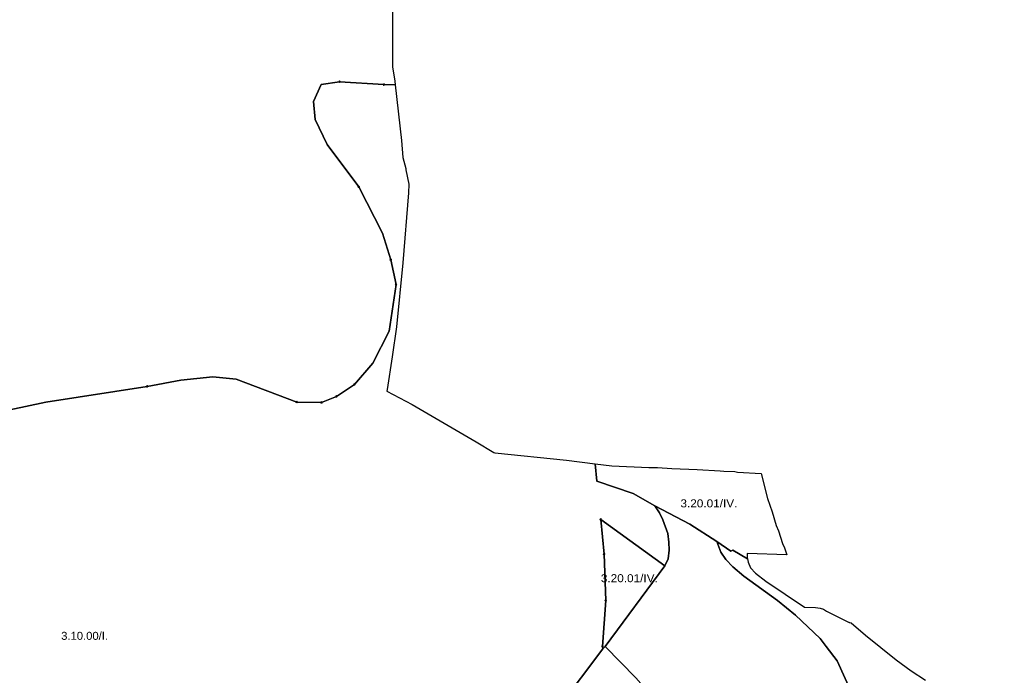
# Model space of a CAD drawing. Extents: x -650455 to -642254, y -1075222 to -1066610.
# Drawn here: x -645652 to -644431, y -1072036 to -1071216 of the extents above; entities that cross this region are included whole.
import ezdxf
from ezdxf.enums import TextEntityAlignment as Align

# ---------------------------------------------------------------- set-up
doc = ezdxf.new("R2010")
doc.units = 0
doc.header["$LTSCALE"] = 4
doc.header["$PDMODE"] = 32
doc.header["$PDSIZE"] = 2
for name, color, linetype, lineweight in [('1', 7, 'Continuous', 25), ('11', 7, 'Continuous', 13), ('12', 7, 'Continuous', 13), ('13', 7, 'Continuous', 13), ('14', 7, 'Continuous', 13)]:
    doc.layers.add(name, color=color, linetype=linetype, lineweight=lineweight)
doc.layers.add('2', color=7, linetype='Continuous')

msp = doc.modelspace()

# ---------------------------------------------------------------- linework, layer by layer
at = {"layer": '1'}
for points in [[(-645186.478, -1071047.655), (-645186.168, -1071275.322), (-645183.374, -1071293.336), (-645182.879, -1071297.884), (-645197, -1071297.501), (-645252.5, -1071294.001), (-645275.5, -1071297.501), (-645285, -1071318.501), (-645283, -1071341), (-645268, -1071372.5), (-645228.5, -1071425.5), (-645199, -1071483.501), (-645188.5, -1071516.501), (-645182, -1071547.5), (-645190.5, -1071606.001), (-645211, -1071646.001), (-645234, -1071672.5), (-645256.5, -1071687.5), (-645275, -1071695.001), (-645306, -1071694.501), (-645381.5, -1071666.001), (-645411, -1071663), (-645451, -1071667.001), (-645493, -1071675.001), (-645619.5, -1071694.501), (-645762.5, -1071725)], [(-645381.5, -1071666.001), (-645306, -1071694.501), (-645275, -1071695.001), (-645256.5, -1071687.5), (-645234, -1071672.5), (-645211, -1071646.001), (-645190.5, -1071606.001), (-645182, -1071547.5), (-645188.5, -1071516.501), (-645199, -1071483.501), (-645228.5, -1071425.5), (-645268, -1071372.5), (-645283, -1071341), (-645285, -1071318.501), (-645275.5, -1071297.501), (-645252.5, -1071294.001), (-645197, -1071297.501), (-645182.879, -1071297.884)], [(-645182.879, -1071297.884), (-645175.302, -1071367.569), (-645173.594, -1071388.835), (-645169.822, -1071402.466), (-645169.513, -1071403.966), (-645165.827, -1071421.836), (-645166.41, -1071432.918), (-645173.6, -1071520.205), (-645181.567, -1071600.493), (-645186.619, -1071637.819), (-645193.199, -1071679.003), (-645193.481, -1071680.767), (-645161.645, -1071697.751), (-645081.726, -1071744.088), (-645059.979, -1071757.758), (-645058.478, -1071757.915), (-644969.167, -1071767.179), (-644933.238, -1071771.647), (-644931.066, -1071793.462), (-644885.697, -1071809.017), (-644858.507, -1071824.054), (-644852.999, -1071832.972), (-644848.802, -1071841.89), (-644842.508, -1071858.851), (-644841.109, -1071869.867), (-644840.584, -1071879.659), (-644841.808, -1071890.5), (-644846.005, -1071899.418), (-644926.312, -1071841.204), (-644922, -1071884.501), (-644920, -1071942.5), (-644924, -1072000), (-644923.589, -1072003.101), (-644978.202, -1072075.468)], [(-645762.5, -1071725), (-645619.5, -1071694.501), (-645493, -1071675.001), (-645451, -1071667.001), (-645411, -1071663), (-645381.5, -1071666.001)], [(-644841.196, -1072085.989), (-644882.287, -1072039.303), (-644920.668, -1072000), (-644846.005, -1071899.418), (-644841.808, -1071890.5), (-644840.584, -1071879.659), (-644841.109, -1071869.867), (-644842.508, -1071858.851), (-644848.802, -1071841.89), (-644852.999, -1071832.972), (-644858.507, -1071824.054), (-644814.968, -1071847.135), (-644781.395, -1071868.992)], [(-644431.857, -1072311.904), (-644430.633, -1072298.615), (-644431.682, -1072288.473), (-644436.403, -1072278.331), (-644453.627, -1072249.305), (-644492.882, -1072176.04), (-644584.42, -1072108.721), (-644596.572, -1072092.634), (-644604.965, -1072074.973), (-644630.931, -1072017.97), (-644644.606, -1072000), (-644652.089, -1071990.168), (-644682.776, -1071960.792), (-644705.508, -1071942.607), (-644747.386, -1071912.357), (-644761.374, -1071900.641), (-644769.942, -1071891.374), (-644776.237, -1071882.107), (-644781.395, -1071868.992), (-644763.822, -1071881.057), (-644761.199, -1071879.659), (-644742.849, -1071890.721)], [(-644781.395, -1071868.992), (-644776.237, -1071882.107), (-644769.942, -1071891.374), (-644761.374, -1071900.641), (-644747.386, -1071912.357), (-644705.508, -1071942.607), (-644682.776, -1071960.792), (-644652.089, -1071990.168), (-644644.606, -1072000), (-644630.931, -1072017.97), (-644604.965, -1072074.973)], [(-644742.849, -1071890.721), (-644742.106, -1071894.882), (-644739.294, -1071901.811), (-644733.02, -1071908.305), (-644720.041, -1071918.372), (-644671.801, -1071950.845), (-644657.871, -1071951.331), (-644651.944, -1071952.178), (-644647.993, -1071953.447), (-644644.042, -1071955.847), (-644616.666, -1071969.818), (-644615.96, -1071969.818), (-644615.819, -1071970.24), (-644613.279, -1071970.664), (-644595.358, -1071985.904), (-644557.257, -1072016.666), (-644538.207, -1072030.496), (-644520.385, -1072042.196)], [(-644978.202, -1072075.468), (-644923.589, -1072003.101), (-644920.668, -1072000), (-644882.287, -1072039.303)]]:
    msp.add_lwpolyline(points, dxfattribs=at)
for points in [[(-644696.536, -1071876.964), (-644693.695, -1071885.72), (-644743.234, -1071883.988), (-644743.22, -1071885.489), (-644743.188, -1071888.822), (-644742.849, -1071890.721), (-644761.199, -1071879.659), (-644763.822, -1071881.057), (-644781.395, -1071868.992), (-644814.968, -1071847.135), (-644858.507, -1071824.054), (-644885.697, -1071809.017), (-644931.066, -1071793.462), (-644933.238, -1071771.647), (-644912.439, -1071774.234), (-644866.154, -1071776.35), (-644855.43, -1071776.493), (-644837.367, -1071777.762), (-644805.758, -1071778.75), (-644776.971, -1071780.443), (-644772.455, -1071781.007), (-644758.908, -1071781.432), (-644755.38, -1071782.136), (-644725.862, -1071783.887), (-644718.089, -1071814.991), (-644712.2, -1071831.95), (-644707.119, -1071848.884), (-644704.297, -1071855.657), (-644699.076, -1071871.462)], [(-644846.005, -1071899.418), (-644920.668, -1072000), (-644923.589, -1072003.101), (-644924, -1072000), (-644920, -1071942.5), (-644922, -1071884.501), (-644926.312, -1071841.204)]]:
    msp.add_lwpolyline(points, close=True, dxfattribs=at)
at = {"layer": '11'}
msp.add_line((-645256.5, -1071687.5), (-645275, -1071695.001), dxfattribs=at)
for points in [[(-645197, -1071297.501), (-645182.879, -1071297.884), (-645183.374, -1071293.336), (-645186.168, -1071275.322), (-645186.478, -1071047.655), (-645173.128, -1071048.276), (-645170.955, -1070998.27), (-645169.092, -1070971.559), (-645147.987, -1070978.586), (-645084.341, -1070986.35), (-645003.309, -1070990.698), (-644922.588, -1070989.767)], [(-645252.5, -1071294.001), (-645275.5, -1071297.501), (-645285, -1071318.501), (-645283, -1071341), (-645268, -1071372.5), (-645228.5, -1071425.5)], [(-645188.5, -1071516.501), (-645199, -1071483.501), (-645228.5, -1071425.5), (-645268, -1071372.5), (-645283, -1071341), (-645285, -1071318.501), (-645275.5, -1071297.501), (-645252.5, -1071294.001), (-645197, -1071297.501)], [(-644922, -1071884.501), (-644926.312, -1071841.204), (-644846.005, -1071899.418), (-644841.808, -1071890.5), (-644840.584, -1071879.659), (-644841.109, -1071869.867), (-644842.508, -1071858.851), (-644848.802, -1071841.89), (-644852.999, -1071832.972), (-644858.507, -1071824.054), (-644885.697, -1071809.017), (-644931.066, -1071793.462), (-644933.238, -1071771.647), (-644969.167, -1071767.179), (-645058.478, -1071757.915), (-645059.979, -1071757.758), (-645081.726, -1071744.088), (-645161.645, -1071697.751), (-645193.481, -1071680.767), (-645193.199, -1071679.003), (-645186.619, -1071637.819), (-645181.567, -1071600.493), (-645173.6, -1071520.205), (-645166.41, -1071432.918), (-645165.827, -1071421.836), (-645169.513, -1071403.966), (-645169.822, -1071402.466), (-645173.594, -1071388.835), (-645175.302, -1071367.569), (-645182.879, -1071297.884), (-645197, -1071297.501), (-645252.5, -1071294.001)], [(-645228.5, -1071425.5), (-645199, -1071483.501), (-645188.5, -1071516.501), (-645182, -1071547.5)], [(-645234, -1071672.5), (-645211, -1071646.001), (-645190.5, -1071606.001), (-645182, -1071547.5), (-645188.5, -1071516.501)], [(-645182, -1071547.5), (-645190.5, -1071606.001), (-645211, -1071646.001), (-645234, -1071672.5), (-645256.5, -1071687.5)], [(-645837, -1071732.5), (-645792, -1071731.001), (-645762.5, -1071725), (-645619.5, -1071694.501), (-645493, -1071675.001), (-645451, -1071667.001), (-645411, -1071663), (-645381.5, -1071666.001), (-645306, -1071694.501)], [(-645275, -1071695.001), (-645306, -1071694.501), (-645381.5, -1071666.001), (-645411, -1071663), (-645451, -1071667.001), (-645493, -1071675.001)], [(-645493, -1071675.001), (-645619.5, -1071694.501), (-645762.5, -1071725), (-645792, -1071731.001), (-645837, -1071732.5), (-645877.5, -1071728), (-645913.5, -1071713), (-645940, -1071694.501), (-645954.5, -1071680.5)], [(-645306, -1071694.501), (-645275, -1071695.001), (-645256.5, -1071687.5), (-645234, -1071672.5)], [(-644924, -1072000), (-644920, -1071942.5), (-644922, -1071884.501)], [(-645000, -1072668.218), (-644963.5, -1072659), (-644952, -1072647.5), (-644985.633, -1072565.416), (-644974.792, -1072562.094), (-644960.629, -1072570.487), (-644946.5, -1072572.001), (-644939, -1072559.5), (-644932, -1072501.001), (-644934, -1072451.501), (-644939.5, -1072388.5), (-644942.5, -1072307.5), (-644938, -1072258.001), (-644932.308, -1072244.028), (-645000, -1072103.795), (-644978.202, -1072075.468), (-644923.589, -1072003.101), (-644924, -1072000)]]:
    msp.add_lwpolyline(points, dxfattribs=at)
for p in [(-645252.5, -1071294.001), (-645197, -1071297.501), (-645228.5, -1071425.5), (-645188.5, -1071516.501), (-645182, -1071547.5), (-645493, -1071675.001), (-645234, -1071672.5), (-645256.5, -1071687.5), (-645306, -1071694.501), (-645275, -1071695.001), (-644922, -1071884.501), (-644924, -1072000)]:
    msp.add_point(p, dxfattribs=at)
at = {"layer": '12'}
msp.add_lwpolyline([(-644604.965, -1072074.973), (-644630.931, -1072017.97), (-644644.606, -1072000), (-644652.089, -1071990.168), (-644682.776, -1071960.792), (-644705.508, -1071942.607), (-644747.386, -1071912.357), (-644761.374, -1071900.641), (-644769.942, -1071891.374), (-644776.237, -1071882.107), (-644781.395, -1071868.992), (-644814.968, -1071847.135), (-644858.507, -1071824.054), (-644852.999, -1071832.972), (-644848.802, -1071841.89), (-644842.508, -1071858.851), (-644841.109, -1071869.867), (-644840.584, -1071879.659), (-644841.808, -1071890.5), (-644846.005, -1071899.418), (-644920.668, -1072000), (-644882.287, -1072039.303)], dxfattribs=at)
at = {"layer": '13'}
for points in [[(-644520.385, -1072042.196), (-644538.207, -1072030.496), (-644557.257, -1072016.666), (-644595.358, -1071985.904), (-644613.279, -1071970.664), (-644615.819, -1071970.24), (-644615.96, -1071969.818), (-644616.666, -1071969.818), (-644644.042, -1071955.847), (-644647.993, -1071953.447), (-644651.944, -1071952.178), (-644657.871, -1071951.331), (-644671.801, -1071950.845), (-644720.041, -1071918.372), (-644733.02, -1071908.305), (-644739.294, -1071901.811), (-644742.106, -1071894.882), (-644742.849, -1071890.721), (-644761.199, -1071879.659), (-644763.822, -1071881.057), (-644781.395, -1071868.992), (-644776.237, -1071882.107), (-644769.942, -1071891.374), (-644761.374, -1071900.641), (-644747.386, -1071912.357), (-644705.508, -1071942.607), (-644682.776, -1071960.792), (-644652.089, -1071990.168), (-644644.606, -1072000), (-644630.931, -1072017.97), (-644604.965, -1072074.973)], [(-644662.318, -1072275.534), (-644684.088, -1072253.327), (-644708.393, -1072229.022), (-644740.129, -1072182.51), (-644750.62, -1072169.92), (-644789.351, -1072136.698), (-644812.607, -1072115.89), (-644841.196, -1072085.989), (-644882.287, -1072039.303), (-644920.668, -1072000), (-644923.589, -1072003.101), (-644978.202, -1072075.468), (-644931.428, -1072113.412), (-644907.123, -1072134.745), (-644885.79, -1072150.832), (-644855.103, -1072180.732), (-644741.009, -1072287.394), (-644719.414, -1072308.552)]]:
    msp.add_lwpolyline(points, dxfattribs=at)
at = {"layer": '14'}
msp.add_line((-644920, -1071942.5), (-644924, -1072000), dxfattribs=at)
msp.add_lwpolyline([(-644781.395, -1071868.992), (-644763.822, -1071881.057), (-644761.199, -1071879.659), (-644742.849, -1071890.721), (-644743.188, -1071888.822), (-644743.22, -1071885.489), (-644743.234, -1071883.988), (-644693.695, -1071885.72), (-644696.536, -1071876.964), (-644699.076, -1071871.462), (-644704.297, -1071855.657), (-644707.119, -1071848.884), (-644712.2, -1071831.95), (-644718.089, -1071814.991), (-644725.862, -1071783.887), (-644755.38, -1071782.136), (-644758.908, -1071781.432), (-644772.455, -1071781.007), (-644776.971, -1071780.443), (-644805.758, -1071778.75), (-644837.367, -1071777.762), (-644855.43, -1071776.493), (-644866.154, -1071776.35), (-644912.439, -1071774.234), (-644933.238, -1071771.647), (-644931.066, -1071793.462), (-644885.697, -1071809.017), (-644858.507, -1071824.054), (-644814.968, -1071847.135)], close=True, dxfattribs=at)
for points in [[(-644924, -1072000), (-644923.589, -1072003.101), (-644920.668, -1072000), (-644846.005, -1071899.418), (-644926.312, -1071841.204)], [(-644926.312, -1071841.204), (-644922, -1071884.501), (-644920, -1071942.5)]]:
    msp.add_lwpolyline(points, dxfattribs=at)
for p in [(-644926.312, -1071841.204), (-644920, -1071942.5), (-644924, -1072000)]:
    msp.add_point(p, dxfattribs=at)

# ---------------------------------------------------------------- texts
at = {"layer": '2'}
for s, width, p in [('3.20.01/IV.', 1.1, (-644791.079, -1071826.169)), ('3.20.01/IV.', 1.1, (-644890.506, -1071919.764)), ('3.10.00/I.', 1.05, (-645571.032, -1071991.808))]:
    msp.add_text(s, height=10, dxfattribs=dict(at, width=width)).set_placement(p, align=Align.CENTER)

doc.saveas('drawing.dxf')
